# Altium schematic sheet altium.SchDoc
size A4
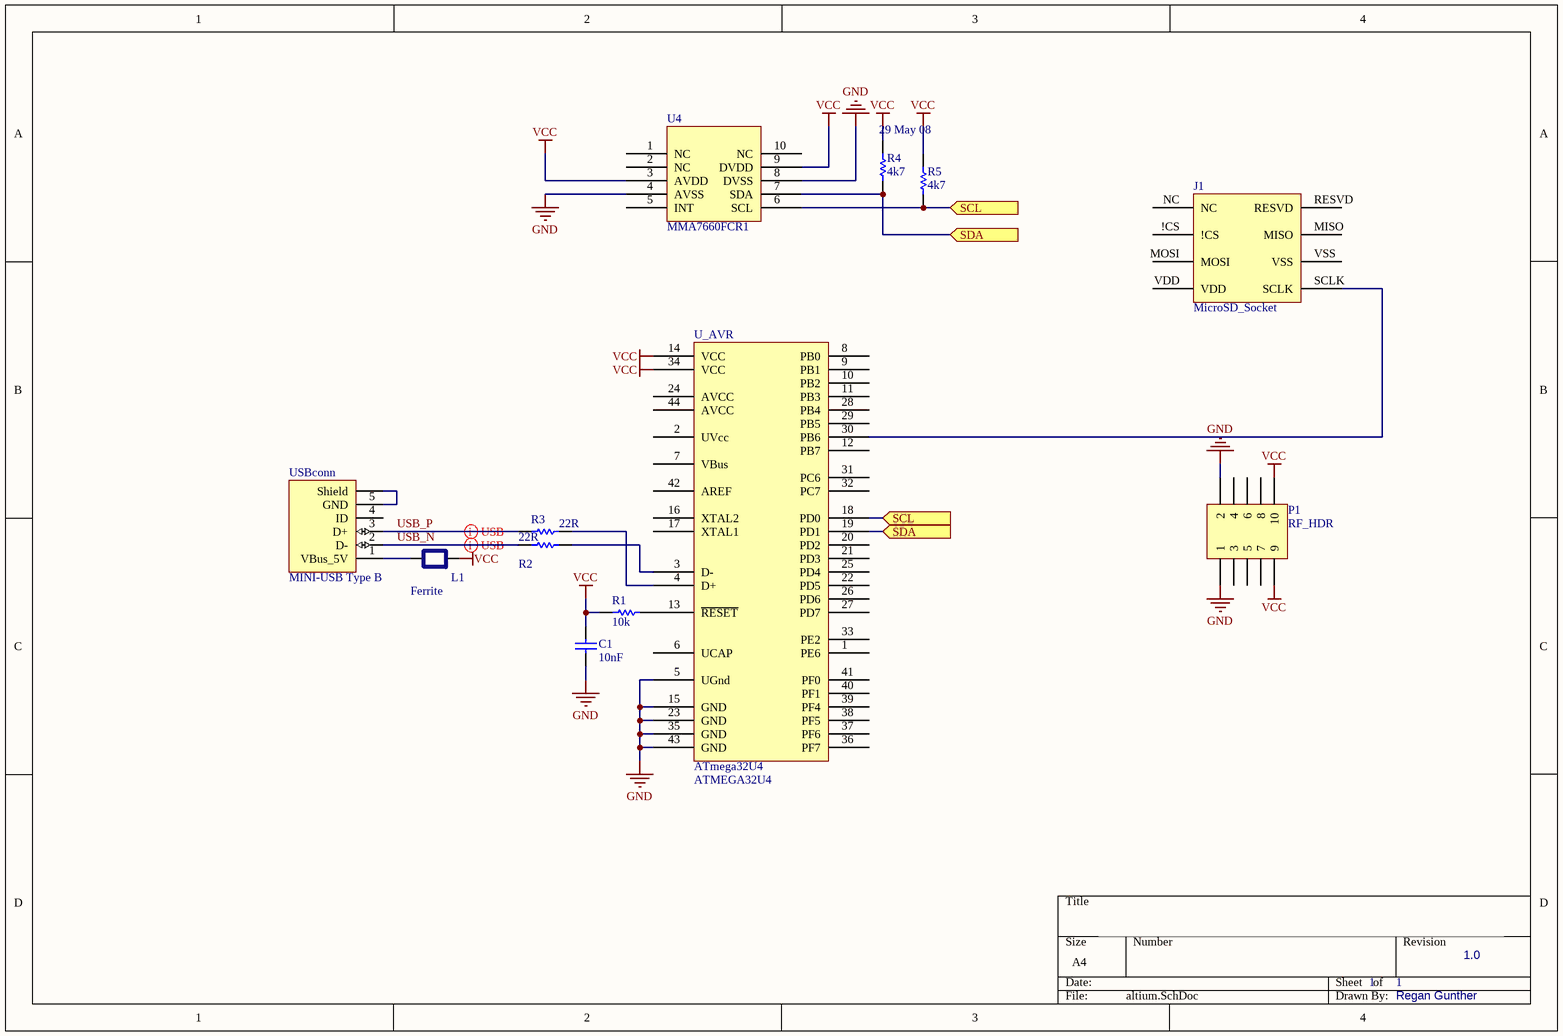
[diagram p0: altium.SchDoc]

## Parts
C1  10nF  [0603]
J1  MicroSD_Socket  [MicroSD]
L1  Ferrite  [0805]
P1  RF_HDR  [Header SMD 2x10 Female]
R1  10k  [0603]
R2  22R  [0603]
R3  22R  [0603]
R4  LatestRevisionDate: 29 May 08  [0603]  (hidden comment: 4k7)
R5  4k7  [0603]
U4  MMA7660FCR1  [DFN-10__MMA7660FCR1]
U_AVR  ATmega32U4  [TQFP-44]
USBconn  MINI-USB Type B  [USB-B SMD]

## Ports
SCL (in), SDA (in)

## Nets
GND: C1.2 P1.1 P1.2 U4.4(AVSS) U4.8(DVSS) U_AVR.5(UGnd) U_AVR.15(GND) U_AVR.23(GND) U_AVR.35(GND) U_AVR.43(GND)
VCC: C1.1 L1.2 P1.9 P1.10 R1.2 R4.2 R5.2 U4.3(AVDD) U4.9(DVDD) U_AVR.14(VCC) U_AVR.34(VCC)
SCL: R5.1 U4.6(SCL) U_AVR.18(PD0) ; port SCL
SDA: R4.1 U4.7(SDA) U_AVR.19(PD1) ; port SDA
USB_N: R2.1 USBconn.2(D-)
USB_P: R3.1 USBconn.3(D+)
NetJ1_SCLK: J1.SCLK U_AVR.30(PB6)
NetL1_1: L1.1 USBconn.1(VBus_5V)
NetR1_1: R1.1 U_AVR.13(~{RESET})
NetR2_2: R2.2 U_AVR.3(D-)
NetR3_2: R3.2 U_AVR.4(D+)
NetUSBconn_5: USBconn.5(GND) USBconn.6(Shield)

Not connected (* = marked no-connect by the designer): J1 !CS MISO MOSI NC RESVD VDD VSS; P1 3 4 5 6 7 8; U4 1(NC) 2(NC) 5(INT) 10(NC); U_AVR 1(PE6) 2(UVcc) 6(UCAP) 7(VBus) 8(PB0) 9(PB1) 10(PB2) 11(PB3) 12(PB7) 16(XTAL2) 17(XTAL1) 20(PD2) 21(PD3) 22(PD5) 24(AVCC) 25(PD4) 26(PD6) 27(PD7) 28(PB4) 29(PB5) 31(PC6) 32(PC7) 33(PE2) 36(PF7) 37(PF6) 38(PF5) 39(PF4) 40(PF1) 41(PF0) 42(AREF) 44(AVCC); USBconn 4(ID)

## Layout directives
differential pair: USB_N, USB_P

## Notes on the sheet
- 2.4GHz Radio Interface Board
- 1
- 1.0
- Regan Gunther

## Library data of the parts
C1 = CP_10nF 0603: CAP CER 10000PF 100V X7R 0603; Manufacturer: Taiyo Yuden; Manufacturer PN: HMK107B7103KA-T
L1 = IN_FERRITE CHIP 120 OHM 800mA 0805: FERRITE CHIP 120 OHM 800mA 0805; Manufacturer: TDK; Manufacturer PN: MMZ2012Y121B
P1 = Header 5X2: Header, 5-Pin, Dual row
R1 = RS_10k 0603: RES 10.0K OHM 1/10W 1% 0603 SMD; Manufacturer: Yageo; Manufacturer PN: RC0603FR-0710KL
R2 R3 = RS_22R 0603: RES 22 OHM 1/10W 1% 0603 SMD; Manufacturer: Yageo; Manufacturer PN: RC0603JR-0722RL
R4 R5 = RS_4k7 0603: RES 4.70K OHM 1/10W 1% 0603 SMD; Manufacturer: ROHM; Manufacturer PN: MCR03EZPFX4701
U_AVR = IC_ATmega32U4_44-TQFP: AVR 8-bit USB microcontroller
USBconn = JP_MINIUSB type B_1: MINI-USB Type B Single Connector; Manufacturer PN: UX60-MB-5ST; Manufacturer: Hirose Electric Co Ltd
